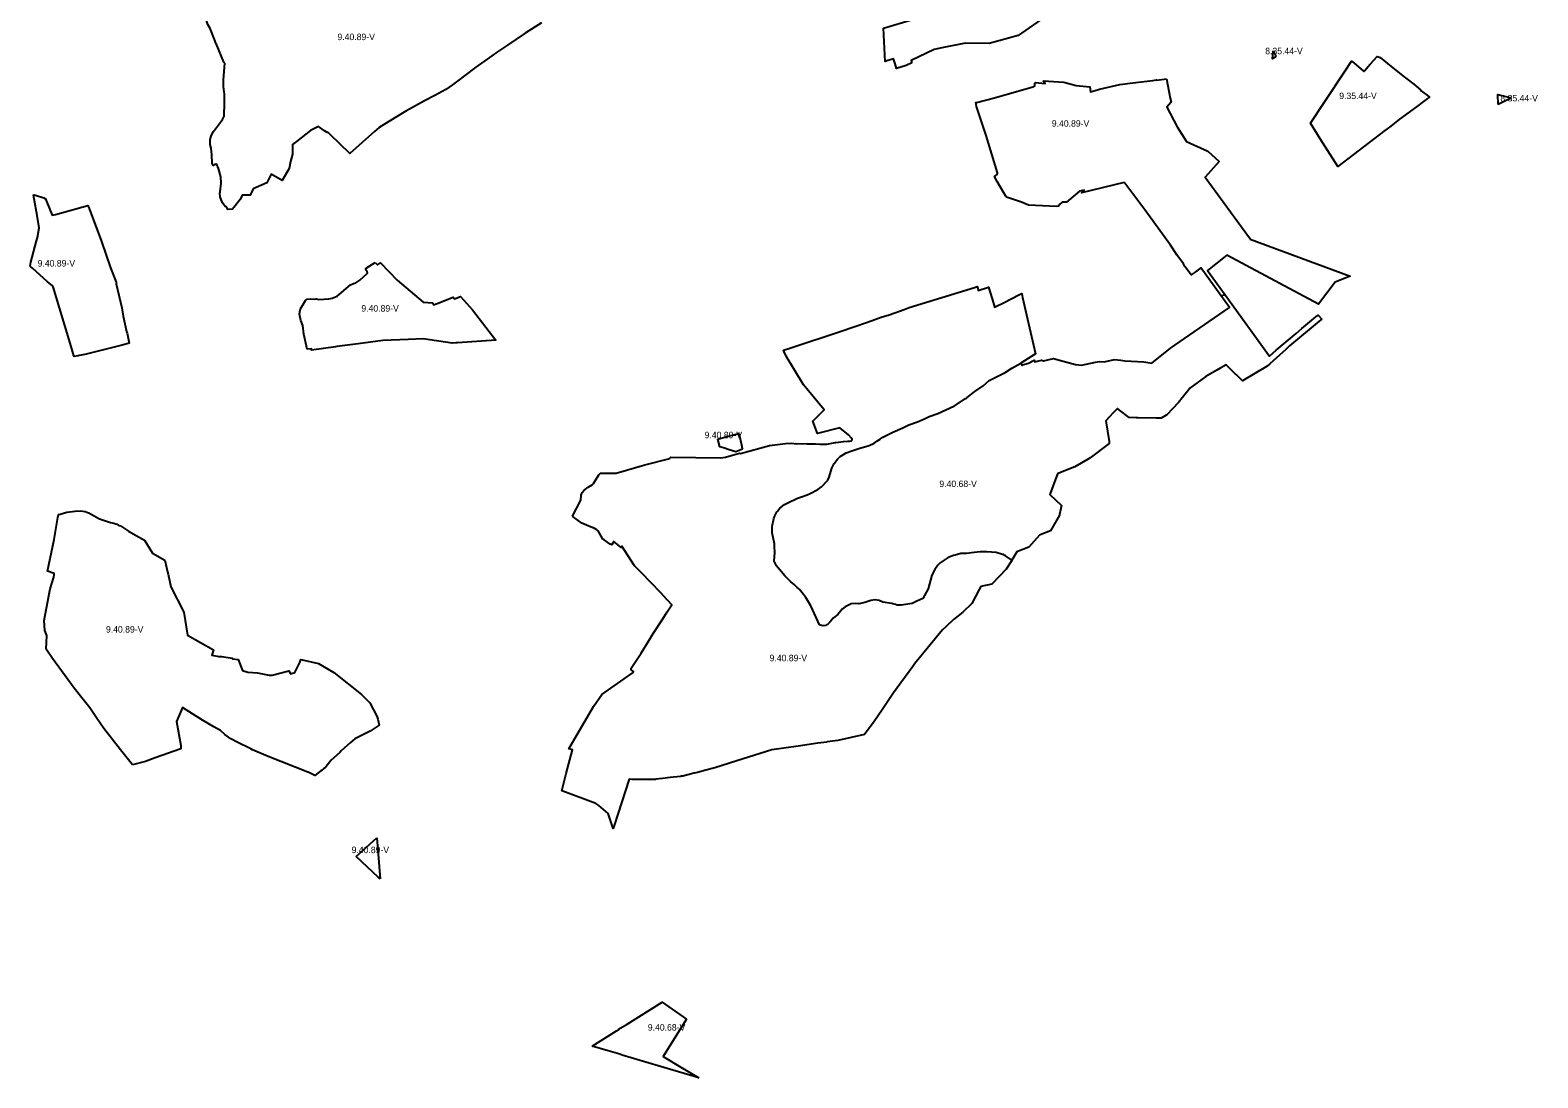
# Model space of a CAD drawing. Extents: x -444937 to -440470, y -1149084 to -1129741.
# Drawn here: x -444937 to -442604, y -1134509 to -1132888 of the extents above; entities that cross this region are included whole.
import ezdxf

# ---------------------------------------------------------------- set-up
doc = ezdxf.new("R2010")
doc.units = 0
doc.layers.add('Vrstva 28', color=7, linetype='Continuous')

msp = doc.modelspace()

# ---------------------------------------------------------------- linework, layer by layer
at = {"layer": 'Vrstva 28'}
for points in [[(-443572.9, -1132938.2), (-443581.63, -1132942.44), (-443596.87, -1132946.92), (-443599.01, -1132939.92), (-443601.31, -1132932.37), (-443611.5, -1132935.48), (-443614.24, -1132936.31), (-443616.98, -1132884.53), (-443527.16, -1132857.75), (-443491.66, -1132827.42), (-443448.67, -1132800.47), (-443374.21, -1132728.14), (-443358.28, -1132759.18), (-443333.67, -1132815.95), (-443332.23, -1132819.25), (-443329.25, -1132826.13), (-443326.96, -1132839.03), (-443408.25, -1132896.1)], [(-444636.01, -1132938.93), (-444637.5, -1132937.44), (-444649.42, -1132908.36), (-444649.58, -1132907.98), (-444650.87, -1132904.79), (-444658.78, -1132885.29), (-444662.19, -1132878.9), (-444666.45, -1132867.41), (-444672.41, -1132855.06), (-444680.92, -1132833.78), (-444701.78, -1132787.37), (-444702.56, -1132785.28)], [(-444146, -1132876.67), (-444171.45, -1132892.73), (-444198.74, -1132911.07), (-444214.15, -1132921.42), (-444222.53, -1132927.36), (-444233.49, -1132935.13), (-444243.71, -1132942.38), (-444249.73, -1132946.65), (-444273.54, -1132964.58), (-444283.75, -1132972.27), (-444293.81, -1132979.85), (-444310.98, -1132989.02), (-444326.73, -1132997.43), (-444350.1, -1133009.92), (-444356.05, -1133013.1), (-444381.89, -1133029.04), (-444397.28, -1133038.54), (-444404.32, -1133044.82), (-444442.24, -1133078.69), (-444472.76, -1133049.31), (-444476.72, -1133045.9), (-444477.64, -1133046.21), (-444481.89, -1133043.87), (-444490.95, -1133036.81), (-444503.49, -1133043.07), (-444525.14, -1133060.19), (-444531.25, -1133064.79), (-444531.28, -1133079.99), (-444534.05, -1133090.9), (-444536.17, -1133101.98), (-444547.23, -1133120.38), (-444564.39, -1133110.9), (-444570.76, -1133124.08), (-444591.78, -1133133.41), (-444596.93, -1133143.03), (-444609.17, -1133143.22), (-444612.07, -1133150.1), (-444623.94, -1133164.86), (-444631.39, -1133165.31), (-444633.18, -1133161.03), (-444633.88, -1133161.16), (-444635.58, -1133160.73), (-444639.41, -1133155.2), (-444642.53, -1133147.58), (-444643.25, -1133145.83), (-444643.67, -1133140.72), (-444643.26, -1133137.89), (-444641.33, -1133124.55), (-444641.97, -1133114.75), (-444645.59, -1133101.98), (-444646.76, -1133099.14), (-444647.5, -1133097.36), (-444648.14, -1133095.81), (-444649.84, -1133095.17), (-444651, -1133095.79), (-444652.15, -1133096.41), (-444654.11, -1133097.45), (-444655.37, -1133094.33), (-444655.8, -1133080.7), (-444656.87, -1133070.48), (-444658.36, -1133064.94), (-444658.36, -1133057.28), (-444656.9, -1133052.11), (-444656.44, -1133050.47), (-444653.25, -1133044.51), (-444639.63, -1133025.99), (-444637.07, -1133021.09), (-444636.55, -1133000), (-444636.22, -1132986.61), (-444636.68, -1132983.46), (-444637.88, -1132975.17), (-444638.14, -1132973.41), (-444638.14, -1132971.69), (-444638.14, -1132964.47), (-444636.01, -1132938.93)], [(-443408.25, -1132896.1), (-443453.46, -1132908.65), (-443490.06, -1132907.88), (-443526.32, -1132915.29), (-443538.36, -1132917.52), (-443573.78, -1132934.82), (-443572.9, -1132938.2)], [(-443010.26, -1132929.41), (-443014.8, -1132931.96), (-443013.74, -1132919.62)], [(-443013.74, -1132919.62), (-443010.14, -1132926.92), (-443010.26, -1132929.41)], [(-442941.41, -1133056.01), (-442956.09, -1133031.53), (-442935.17, -1133000), (-442902.35, -1132950.54), (-442892.51, -1132935.72), (-442889.26, -1132938.29), (-442873.93, -1132951.06), (-442873.08, -1132951.28), (-442872.23, -1132950.43), (-442867.36, -1132944.37), (-442863.61, -1132940.46), (-442863.33, -1132940.17), (-442852.86, -1132928.5), (-442848.39, -1132929.99), (-442831.36, -1132944.25)], [(-443094.96, -1133298.48), (-443120.42, -1133263.45), (-443125.81, -1133255.89), (-443136.18, -1133263.55), (-443141.01, -1133266.45), (-443150.44, -1133253.54), (-443152.78, -1133249.28), (-443163, -1133235.66), (-443173, -1133220.34), (-443212.59, -1133165.84), (-443224.8, -1133149.51), (-443243.46, -1133124.55), (-443244.58, -1133123.8), (-443310.66, -1133139.37), (-443306.22, -1133135.63), (-443313.55, -1133137.18), (-443333.78, -1133153.98), (-443340.15, -1133153.82), (-443343.86, -1133157.33), (-443345.21, -1133158.61), (-443346.06, -1133160.31), (-443349.04, -1133160.95), (-443392.46, -1133158.61), (-443403.53, -1133153.92), (-443426.4, -1133146.43), (-443427.54, -1133144.54), (-443430.46, -1133139.68), (-443440.97, -1133122.17), (-443444.83, -1133114.12), (-443441, -1133111.35), (-443440.36, -1133108.8), (-443457.81, -1133050.9), (-443472.71, -1133005.77), (-443473.97, -1133000), (-443473.08, -1133000), (-443445.25, -1132992.78), (-443385.65, -1132975.54), (-443382.67, -1132973.84), (-443382.88, -1132969.8), (-443381.82, -1132968.94), (-443366.56, -1132970.39), (-443369.33, -1132966.47), (-443337.73, -1132968.38), (-443318.5, -1132973.23), (-443297.79, -1132975.44), (-443296.43, -1132983.04), (-443289.25, -1132981.03), (-443282.63, -1132979.16), (-443251.12, -1132971.92), (-443231.27, -1132969.44), (-443200.04, -1132965.54), (-443194.19, -1132964.88), (-443194.14, -1132965.07), (-443179.15, -1132962.93)], [(-443179.15, -1132962.93), (-443173.49, -1132993.25), (-443171.6, -1132999), (-443172.37, -1132999.26), (-443172.25, -1132999.92), (-443178.65, -1133006.98), (-443162.26, -1133037.43), (-443148.19, -1133059.98), (-443114.76, -1133075.24), (-443097.28, -1133090.91), (-443118.98, -1133115.33), (-443050.8, -1133209.14), (-443049.39, -1133211.2), (-442894.94, -1133268.62), (-442917.79, -1133278.04), (-442943.64, -1133311.8), (-443085.5, -1133235.99), (-443115.7, -1133259.74), (-443088.41, -1133297.31)], [(-442831.36, -1132944.25), (-442811.19, -1132959.99), (-442809.1, -1132961.63), (-442796.45, -1132971.5), (-442786.23, -1132980.01), (-442784.74, -1132981.93), (-442775.16, -1132988.95), (-442771.86, -1132991.37), (-442774.95, -1132993.64), (-442783.63, -1133000), (-442790.11, -1133004.75), (-442803.68, -1133014.71), (-442818.23, -1133025.8), (-442831.83, -1133036.16), (-442837.31, -1133040.33), (-442841.05, -1133043.18), (-442913.98, -1133098.76), (-442941.41, -1133056.01)], [(-442665.82, -1133002.63), (-442666.32, -1132987.26), (-442645.79, -1132992.69)], [(-442648.47, -1132994.02), (-442665.82, -1133002.63)], [(-442645.79, -1132992.69), (-442648.47, -1132994.02)], [(-444937.07, -1133253.08), (-444935.79, -1133246.77), (-444927.2, -1133213.81), (-444927.19, -1133213.79), (-444925.81, -1133208.5), (-444922.98, -1133193.59), (-444922.98, -1133193.57), (-444926.06, -1133174.74), (-444931.04, -1133148.77), (-444931.51, -1133146.3), (-444932.13, -1133142.48)], [(-444932.13, -1133142.48), (-444930.97, -1133142.82), (-444927.26, -1133143.92), (-444915.71, -1133147.32), (-444913.58, -1133149.03), (-444911.35, -1133154.3)], [(-444911.35, -1133154.3), (-444902.91, -1133174.23), (-444898.1, -1133173.07), (-444888.46, -1133170.74), (-444847.78, -1133158.97), (-444845.99, -1133163.68), (-444826.52, -1133214.8), (-444812.68, -1133255.67), (-444804.17, -1133277.81), (-444804.17, -1133280.36), (-444795.23, -1133317.83), (-444793.31, -1133330.6), (-444787.99, -1133354.44), (-444786.93, -1133356.99), (-444784, -1133372.32), (-444785.65, -1133372.75), (-444796.93, -1133375.67), (-444802.89, -1133377.22), (-444852.28, -1133389.56), (-444861.06, -1133391.41), (-444862.76, -1133391.77), (-444868.94, -1133393.07), (-444869.3, -1133391.9), (-444873.77, -1133377.64), (-444901.45, -1133285.04), (-444901.73, -1133284.69), (-444903.15, -1133282.92), (-444910.05, -1133277.27), (-444933.59, -1133256.31), (-444935.64, -1133254.41), (-444937.02, -1133253.12), (-444937.07, -1133253.08)], [(-444429.38, -1133373.23), (-444462.39, -1133377.64), (-444464.82, -1133377.96), (-444501.63, -1133382.88), (-444502.02, -1133381.11), (-444508.51, -1133381.69), (-444513.4, -1133358.27), (-444515.1, -1133345.07), (-444518.51, -1133336.98), (-444520.42, -1133327.62), (-444520.3, -1133326.91), (-444519.3, -1133321.2), (-444518.93, -1133319.1), (-444511.27, -1133306.33), (-444508.71, -1133304.42), (-444503.18, -1133303.78), (-444497.22, -1133304.2), (-444494.67, -1133303.78), (-444490.41, -1133304.63), (-444475.08, -1133303.78), (-444469.97, -1133302.5), (-444462.31, -1133299.31), (-444459.12, -1133297.18), (-444441.66, -1133281.85), (-444436.77, -1133279.72), (-444433.36, -1133279.08), (-444426.98, -1133274.83), (-444415.27, -1133263.76), (-444415.48, -1133261.63), (-444417.61, -1133258.65), (-444417.82, -1133256.95), (-444417.18, -1133256.1), (-444403.24, -1133247.54)], [(-444403.24, -1133247.54), (-444399.81, -1133250.87), (-444395.18, -1133248.07), (-444369.03, -1133274.55), (-444342.48, -1133297.4), (-444328.94, -1133309.05), (-444314.65, -1133309.75), (-444312.8, -1133312.89), (-444307.35, -1133311.02), (-444282.77, -1133300.92), (-444280.58, -1133303.85), (-444271.02, -1133300.16), (-444252.68, -1133320.93), (-444216.74, -1133367.38), (-444275.65, -1133371.89), (-444278.43, -1133371.5), (-444284.36, -1133372.11), (-444328.82, -1133365.8), (-444352.27, -1133366.68), (-444391.21, -1133368.13), (-444429.38, -1133373.23)], [(-443868.25, -1133549.81), (-443861.5, -1133548.73), (-443859.5, -1133548.12), (-443850.54, -1133545.38), (-443839.69, -1133542.61), (-443838.2, -1133542.82), (-443793.07, -1133530.69), (-443768.38, -1133527.71), (-443758.8, -1133527.28), (-443752.14, -1133527.82), (-443751.79, -1133527.75), (-443734.98, -1133528.06), (-443722.17, -1133528.3), (-443715.07, -1133528.43), (-443705.01, -1133528.61), (-443704.54, -1133528.74), (-443691.68, -1133526.24), (-443690.47, -1133526.01), (-443678.55, -1133524.3), (-443672.1, -1133523.98), (-443670.04, -1133523.88), (-443669.25, -1133524.04), (-443666.36, -1133523.37), (-443665.95, -1133523.13), (-443665.78, -1133523.03), (-443665.14, -1133520.9), (-443665.99, -1133519.41), (-443666.13, -1133519.26), (-443670.89, -1133514.3), (-443684.16, -1133503.16), (-443718.75, -1133511.94), (-443726.28, -1133492.98), (-443708.62, -1133475.23), (-443735.41, -1133442.77), (-443740.49, -1133436.6), (-443767.53, -1133392.33), (-443770.3, -1133385.73), (-443771.34, -1133383.24), (-443763.4, -1133380.59), (-443679.42, -1133352.48), (-443665.85, -1133347.95), (-443658.12, -1133345.37), (-443634.27, -1133337.41), (-443620.65, -1133332.09), (-443607.88, -1133328.26), (-443584.85, -1133319.94), (-443577.23, -1133317.19), (-443475.91, -1133285.9), (-443471.85, -1133284.74), (-443471.11, -1133287.61)], [(-443471.11, -1133287.61), (-443470.35, -1133290.54), (-443454.38, -1133285.54), (-443448.87, -1133303.46), (-443444.97, -1133316.17), (-443444.85, -1133316.56), (-443430.35, -1133309.52), (-443407.36, -1133297.39), (-443403, -1133295.39), (-443401.63, -1133301.42), (-443381.63, -1133388.88), (-443404.19, -1133403.1)], [(-443404.19, -1133403.1), (-443402.26, -1133406.59), (-443401.83, -1133405.95), (-443392.46, -1133403.4), (-443392.29, -1133403.36), (-443383.54, -1133398.38), (-443382.83, -1133401.17), (-443372.24, -1133398.71), (-443369.18, -1133399.63), (-443353.96, -1133396.01), (-443344.3, -1133398.7), (-443319.92, -1133405.43), (-443310.55, -1133406.35), (-443288.59, -1133401.69), (-443282.63, -1133400.84), (-443275.55, -1133401.12), (-443259.58, -1133397.55), (-443249.86, -1133398.75), (-443243.57, -1133399.52), (-443213.83, -1133401.21), (-443201.64, -1133403.07), (-443172.68, -1133379.8), (-443150.93, -1133364.95), (-443081.35, -1133317.21), (-443094.96, -1133298.48)], [(-443094.96, -1133298.48), (-443088.41, -1133297.31)], [(-443088.41, -1133297.31), (-443019.4, -1133392.29), (-443009.31, -1133383.18), (-442978.41, -1133357.21), (-442969.47, -1133349.7), (-442948.01, -1133331.66), (-442944.55, -1133328.91), (-442938.71, -1133335.38)], [(-442938.71, -1133335.38), (-442942.97, -1133338.41), (-442988.43, -1133376.53), (-442994.29, -1133381.86), (-443004.16, -1133390.84), (-443013.97, -1133399.77), (-443019.22, -1133404.34), (-443023.3, -1133407.89), (-443061.54, -1133430.72), (-443071.36, -1133421.02), (-443072.87, -1133419.53), (-443080.48, -1133411.79), (-443086.42, -1133405.74), (-443094.72, -1133410.46), (-443100.89, -1133413.98), (-443117.97, -1133423.7), (-443142.99, -1133442.12), (-443145.6, -1133445.39), (-443156.78, -1133459.41), (-443157.19, -1133459.92), (-443158.2, -1133461.19), (-443159, -1133462.19), (-443160.05, -1133463.34), (-443160.54, -1133463.87), (-443178.2, -1133483.16), (-443187.15, -1133488.51), (-443195.08, -1133488.36), (-443222.99, -1133487.82), (-443225.82, -1133487.77), (-443236.62, -1133487.56), (-443251.53, -1133475.95), (-443254.81, -1133473.39), (-443261.98, -1133480.82), (-443273.06, -1133492.3), (-443267.92, -1133524.6), (-443267.46, -1133527.46), (-443297.21, -1133549.88), (-443301.34, -1133552.35), (-443320.58, -1133563.84), (-443345.72, -1133573.72), (-443347.77, -1133574.52), (-443359.36, -1133606.47), (-443341.31, -1133623.39), (-443344.39, -1133637.34), (-443344.65, -1133638.54), (-443358.28, -1133662.84), (-443365.32, -1133665.52), (-443375.33, -1133669.32), (-443391.72, -1133688.25), (-443410.29, -1133695.35), (-443416.48, -1133705.44), (-443418.1, -1133708.08)], [(-443651.73, -1133534.31), (-443651.56, -1133534.26), (-443638.96, -1133530.9), (-443631.3, -1133526.86), (-443627.13, -1133524.12), (-443622.08, -1133520.81), (-443621.45, -1133520.4), (-443617.67, -1133517.92), (-443608.49, -1133513.07), (-443602.35, -1133509.83), (-443587.02, -1133503.44), (-443577.65, -1133498.76), (-443564.03, -1133494.08), (-443552.37, -1133488.8), (-443546.15, -1133485.99), (-443532.53, -1133481.09), (-443507.84, -1133469.6), (-443507.71, -1133469.52), (-443489.95, -1133457.68), (-443488.25, -1133457.25), (-443487.18, -1133456.41), (-443475.48, -1133447.25), (-443462.71, -1133438.31), (-443453.34, -1133430), (-443446.98, -1133427.12), (-443431.76, -1133419.09), (-443428.65, -1133417.45), (-443418.01, -1133411.21), (-443404.19, -1133403.1)], [(-443835.2, -1133536.35), (-443845.5, -1133540.58), (-443855.44, -1133537.32), (-443862.59, -1133534.97), (-443869.96, -1133532.55), (-443873.28, -1133520.72), (-443860.52, -1133517.21), (-443844.74, -1133512.87), (-443840.51, -1133511.71), (-443836.61, -1133529.61)], [(-443836.61, -1133529.61), (-443835.37, -1133535.55), (-443835.2, -1133536.35)], [(-443418.1, -1133708.08), (-443428.25, -1133701.34), (-443429.28, -1133700.89), (-443430.93, -1133699.6), (-443432.91, -1133699.28), (-443442.27, -1133696.3), (-443456.75, -1133695.23), (-443461.58, -1133695.33), (-443467.18, -1133695.44), (-443476.33, -1133696.08), (-443488.25, -1133698), (-443496.98, -1133698), (-443505.98, -1133700.21), (-443508.26, -1133700.77), (-443516.56, -1133704.17), (-443528.91, -1133712.47), (-443532.53, -1133715.88), (-443537.42, -1133722.69), (-443541.89, -1133731.21), (-443547.85, -1133752.49), (-443555.82, -1133767.38), (-443565.16, -1133771.67), (-443572.55, -1133775.06), (-443589.57, -1133777.82), (-443590.26, -1133777.8), (-443595.53, -1133777.61), (-443598.22, -1133776.77), (-443602.35, -1133775.48), (-443604.09, -1133775.21), (-443617.67, -1133773.14), (-443623.63, -1133770.8), (-443629.59, -1133769.73), (-443636.62, -1133770.37), (-443642.4, -1133772.52), (-443645.77, -1133773.78), (-443652.51, -1133775.31), (-443654.95, -1133775.86), (-443655.14, -1133775.91), (-443660.46, -1133775.06), (-443667.06, -1133775.91), (-443676.21, -1133780.38), (-443680.47, -1133783.57), (-443683.12, -1133786.89), (-443687.28, -1133792.08), (-443694.09, -1133797.62), (-443700.03, -1133804.34), (-443702.18, -1133806.77), (-443705.42, -1133808.82), (-443706.22, -1133809.33), (-443710.27, -1133809.75), (-443714.1, -1133808.48), (-443716.23, -1133806.98), (-443720.43, -1133798.03), (-443729.42, -1133778.89), (-443736.87, -1133766.11), (-443742.41, -1133758.45), (-443746.67, -1133753.56), (-443747.78, -1133752.56), (-443750.18, -1133750.41), (-443755.12, -1133745.99), (-443759.97, -1133741.65), (-443764.97, -1133737.17), (-443769.25, -1133732.28), (-443777.86, -1133722.44), (-443778.38, -1133721.84), (-443782.22, -1133716.73), (-443786.06, -1133709.67), (-443784.77, -1133696.3), (-443785.34, -1133687.1), (-443785.62, -1133682.67), (-443788.81, -1133665.64), (-443789.03, -1133655.43), (-443788.62, -1133653.52), (-443787.05, -1133646.2), (-443786.47, -1133643.51), (-443785.19, -1133639.67), (-443781.79, -1133633.29), (-443780.86, -1133632.14), (-443777.32, -1133627.75), (-443770.08, -1133622.22), (-443765.61, -1133619.98), (-443749.65, -1133612), (-443743.69, -1133610.3), (-443735.03, -1133606.78), (-443730.06, -1133604.76), (-443718.36, -1133598.8), (-443712.61, -1133594.76), (-443703.43, -1133584.97), (-443703.03, -1133584.54), (-443700.69, -1133579.43), (-443696.64, -1133565.81), (-443694.76, -1133561.69), (-443693.24, -1133558.36), (-443688.13, -1133551.55), (-443684.09, -1133547.93), (-443678.95, -1133544.54), (-443674.72, -1133541.76), (-443665.83, -1133538.88), (-443651.73, -1133534.31)], [(-443631.11, -1133957.59), (-443646.25, -1133977.94), (-443687.69, -1133987.12), (-443703.87, -1133989.45), (-443704.63, -1133989.56), (-443718.38, -1133991.55), (-443748.6, -1133995.92), (-443789.33, -1134001.75), (-443843.9, -1134018.78), (-443877.9, -1134029.38), (-443891.57, -1134032.98), (-443904.67, -1134036.7), (-443909.78, -1134037.97), (-443910.14, -1134037.88), (-443914.12, -1134038.93), (-443927.02, -1134042.33), (-443929.31, -1134042.59), (-443931.06, -1134043.08), (-443946.66, -1134044.53), (-443958.7, -1134045.88), (-443968.7, -1134047), (-443969.37, -1134047.34), (-443973.63, -1134047.76), (-444006.06, -1134047.38), (-444010.18, -1134047.33), (-444033.66, -1134118.74), (-444035.26, -1134123.58), (-444042.58, -1134100.33), (-444057.05, -1134087.99), (-444061.95, -1134084.79), (-444112.69, -1134065.74), (-444114.37, -1134065.11), (-444107.92, -1134038.19), (-444097.91, -1134001.58), (-444103.59, -1134000), (-444065.53, -1133934.49), (-444052.34, -1133915.97), (-444004.23, -1133881.91), (-444003.8, -1133880.64), (-444007.21, -1133877.66), (-444007.21, -1133875.53), (-443991.67, -1133852.11), (-443979.54, -1133831.89), (-443972.95, -1133821.66), (-443958.43, -1133799.13), (-443951.39, -1133788.2), (-443944.39, -1133777.33), (-443957.22, -1133763.13), (-443961.45, -1133758.45), (-443991.46, -1133727.65), (-444002.1, -1133716.73), (-444021.69, -1133686.24), (-444022.52, -1133688.35), (-444034.04, -1133679.28), (-444037.22, -1133684.16), (-444039.57, -1133683.31), (-444049.15, -1133676.86), (-444051.27, -1133675.44), (-444056.32, -1133666.41), (-444058.3, -1133662.88), (-444058.99, -1133662.25), (-444060.43, -1133660.96), (-444065.53, -1133658.19), (-444066.28, -1133657.88), (-444072.46, -1133655.31), (-444083.42, -1133650.74), (-444096.75, -1133640.82), (-444097.94, -1133639.93), (-444085.33, -1133615.41), (-444084.48, -1133607.75), (-444083.2, -1133603.49), (-444080.44, -1133600.08), (-444073.84, -1133595.19), (-444067.66, -1133591.78), (-444065.32, -1133589.44), (-444057.02, -1133575.82), (-444054.88, -1133573.36), (-444043.34, -1133573.51), (-444030.2, -1133573.69), (-443985.93, -1133560.7), (-443949.31, -1133551.12), (-443947.18, -1133550.49), (-443945.78, -1133548.96), (-443868.25, -1133549.81)], [(-444912.07, -1133845.63), (-444911.45, -1133824.87), (-444914.59, -1133817.07), (-444915.18, -1133801.41), (-444906.05, -1133752.26), (-444900.35, -1133734.6), (-444900.02, -1133730.84), (-444899.67, -1133728.93), (-444910.08, -1133725.03), (-444900.17, -1133676.29), (-444894, -1133642.23), (-444893.12, -1133637.38), (-444890.59, -1133636.7), (-444880.37, -1133633.93), (-444867.6, -1133632.22), (-444859.3, -1133631.8), (-444851.85, -1133632.86)], [(-444851.85, -1133632.86), (-444846.91, -1133634.84), (-444846.42, -1133634.77), (-444842.71, -1133636.98), (-444829.71, -1133644.36), (-444816.09, -1133649.04), (-444812.78, -1133649.7), (-444807.57, -1133650.74), (-444802.89, -1133652.66), (-444799.81, -1133654.58), (-444797.1, -1133655.22), (-444784.82, -1133663.08), (-444773.19, -1133669.73), (-444760.35, -1133676.92), (-444747.91, -1133697.35), (-444728.74, -1133707.96), (-444724.5, -1133726.4), (-444723.74, -1133729.69), (-444719.19, -1133749.46), (-444699.46, -1133788.71), (-444693.74, -1133824.19), (-444653.42, -1133846.86), (-444655.94, -1133855.21), (-444644.95, -1133857.43), (-444640.69, -1133857.43), (-444624.44, -1133859.69), (-444624.09, -1133860.62), (-444615.4, -1133861.8), (-444608.64, -1133878.98), (-444600.17, -1133881.65), (-444585.13, -1133882.34), (-444567.04, -1133886.17), (-444562.78, -1133885.96), (-444536.82, -1133879.47), (-444534.47, -1133883.61), (-444534.26, -1133884.04), (-444527.5, -1133882.02), (-444520.09, -1133866.25), (-444518.13, -1133862.07), (-444491.12, -1133868.12), (-444467.02, -1133882.2), (-444424.22, -1133916.06), (-444411.7, -1133928.91), (-444399.96, -1133950.77), (-444399.09, -1133954.4), (-444396.88, -1133963.73), (-444410.85, -1133972.54), (-444434.62, -1133984.4), (-444441.85, -1133990.81), (-444455.3, -1134002.74), (-444457.74, -1134005.97), (-444471.42, -1134017.75), (-444480.57, -1134029.67), (-444482.67, -1134030.64), (-444486.35, -1134033.46), (-444487.17, -1134034.14), (-444487.6, -1134034.42), (-444496.8, -1134041.46), (-444507.08, -1134036.39), (-444507.31, -1134036.3), (-444568.69, -1134011.74), (-444593.16, -1134001.79), (-444595.54, -1134000), (-444616.68, -1133989.62), (-444626.64, -1133984.73), (-444636.01, -1133977.91), (-444642.82, -1133971.95), (-444652.87, -1133966.29), (-444670.49, -1133955.99), (-444701.19, -1133935.93), (-444710.67, -1133957.59), (-444703.95, -1133994.97), (-444704.19, -1134000), (-444743.46, -1134014.25), (-444758.51, -1134019.72), (-444778.65, -1134024.9)], [(-443418.1, -1133708.08), (-443418.37, -1133708.52), (-443427.09, -1133722.11), (-443449.43, -1133745.05), (-443466.21, -1133748.87), (-443468.58, -1133753.29), (-443480.24, -1133774.99), (-443494.1, -1133788.49), (-443508.55, -1133799.78), (-443519.86, -1133810.93), (-443525.44, -1133816.12), (-443568.24, -1133868.28), (-443571.4, -1133872.62), (-443601.28, -1133913.69), (-443619.02, -1133939.8), (-443631.11, -1133957.59)], [(-444778.65, -1134024.9), (-444797.25, -1134001.66), (-444823, -1133968.9), (-444834.3, -1133952.04), (-444844.6, -1133936.67), (-444857.19, -1133921.02), (-444869.15, -1133906.24), (-444902.38, -1133860.41), (-444912.07, -1133845.63)], [(-444432.66, -1134166.63), (-444400.84, -1134138.04)], [(-444400.84, -1134138.04), (-444395.64, -1134201.14)], [(-444395.64, -1134201.14), (-444398.84, -1134198.88), (-444432.66, -1134166.63)], [(-444067.31, -1134460.16), (-444030.11, -1134436.35), (-444030.09, -1134436.5), (-444029.99, -1134436.45), (-444026.13, -1134434.52), (-444026.58, -1134434.14), (-444013.22, -1134426.27), (-443959.47, -1134392.43), (-443921.49, -1134418.49)], [(-443921.49, -1134418.49), (-443950.98, -1134465.62), (-443957.82, -1134476.55), (-443930.2, -1134493), (-443916.5, -1134501.1), (-443902.55, -1134509.36)], [(-443902.55, -1134509.36), (-443965.29, -1134490.62), (-444020.89, -1134474.03), (-444024.75, -1134472.85), (-444042.77, -1134467.48), (-444067.31, -1134460.16)]]:
    msp.add_lwpolyline(points, dxfattribs=at)

# ---------------------------------------------------------------- texts
for s, p in [('9.40.89-V', (-444461.65, -1132903.23)), ('8.35.44-V', (-443026.22, -1132925.05)), ('9.35.44-V', (-442911.67, -1132994.48)), ('8.35.44-V', (-442662.36, -1132998.11)), ('9.40.89-V', (-443356.39, -1133037.26)), ('9.40.89-V', (-444925.54, -1133253.7)), ('9.40.89-V', (-444424.66, -1133323.43)), ('9.40.89-V', (-443893.59, -1133519.44)), ('9.40.68-V', (-443530.38, -1133594.98)), ('9.40.89-V', (-444819.81, -1133820.2)), ('9.40.89-V', (-443793.03, -1133864.56)), ('9.40.89-V', (-444439.72, -1134161.57)), ('9.40.68-V', (-443981.42, -1134436.23))]:
    msp.add_text(s, height=10, dxfattribs=at).set_placement(p)

doc.saveas('drawing.dxf')
